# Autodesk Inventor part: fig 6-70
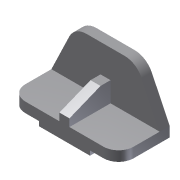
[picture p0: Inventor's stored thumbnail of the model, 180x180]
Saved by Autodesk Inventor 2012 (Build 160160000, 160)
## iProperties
Shininess: 77.0
Length Units: 11269
Angle Units: 11279
Time Units: 11290
Mass Units: 11283
Length Display Precision: 3
Angle Display Precision: 2
Created: 2001-12
Part Number: fig 6-70
Document SubType Name: Modeling
Designer: Renu Muthoo
Density: 1 g/cm^3
Material: Default
Density: 0.0
Volumn: 0.0
Area: 0.0
PropertySet Name: Model Information
Control State: 0
Master: False
Checked Out: False
Author: Renu Muthoo
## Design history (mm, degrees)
sketch "Sketch2"
  geometry: L1 (-67.219, 19.116)-(148.781, 19.116); L2 (148.781, 19.116)-(148.781, -0.884); L3 (-67.219, -0.884)-(-67.219, 19.116); L4 (-10.219, -0.884)-(-10.219, -9.884); L5 (-10.219, -9.884)-(91.781, -9.884); L6 (91.781, -9.884)-(91.781, -0.884); L7 (148.781, -0.884)-(91.781, -0.884); L8 (-10.219, -0.884)-(-67.219, -0.884)
  constraints: 16 end point, 5 parallel, 4 perpendicular, 2 equal length, 1 horizontal
  dimensions: "d0" = 102 distance of L4.end L5.end; "d1" = 57 distance of L4.start L3.start; "d2" = 29 distance between parallel lines of L1 L5; "d3" = 20 distance of L1.end L2.end
extrude "Extrusion1" new body sketch "Sketch2" distance "d4" = 102; taper "d5" = 0 deg
sketch "Sketch3"
  geometry: L1 (67.219, -19.116)-(-148.781, -19.116) reference; L2 (67.219, -19.116)-(31.475, -93.564); L3 (-2.781, -115.116)-(-78.781, -115.116); L4 (-113.038, -93.564)-(-148.781, -19.116); A1 r 38 centre (-2.781, -77.116) between (-2.781, -115.116) and (31.475, -93.564); A2 r 38 centre (-78.781, -77.116) between (-113.038, -93.564) and (-78.781, -115.116)
  constraints: 6 end point, 4 point on circle, 4 tangent, 2 centre point, 1 equal length, 1 equal radius, 1 parallel
  dimensions: "d6" = 96 distance between parallel lines of L3 L1; "d7" = 38 radius of A1; "d8" = 76 distance of A2.centre A1.centre
extrude "Extrusion2" join sketch "Sketch3" distance "d9" = 20; taper "d10" = 0 deg
fillet "Fillet1" dims "d11" = 30
workplane "Work Plane1"
sketch "Sketch7"
  geometry: L1 (0, -82)-(-15, -82); L2 (-15, -82)-(-40, -20); L3 (-40, -20)-(-40, 0); L4 (0, -82)-(20, -82) reference; L5 (0, 0)-(-74.447, 0) reference
  constraints: 6 end point, 2 point on line, 1 horizontal, 1 perpendicular
  dimensions: "d32" = 20 distance of L2.end L3.end; "d33" = 15 distance of L1.start L1.end; "d34" = 40 distance of L5.start L3.end
feature "Rib4" sketch "Sketch7" dims "d55" = 1, "d56" = 20, "d57" = 0
body "Solid1"
other parameters: "d12" = -108
